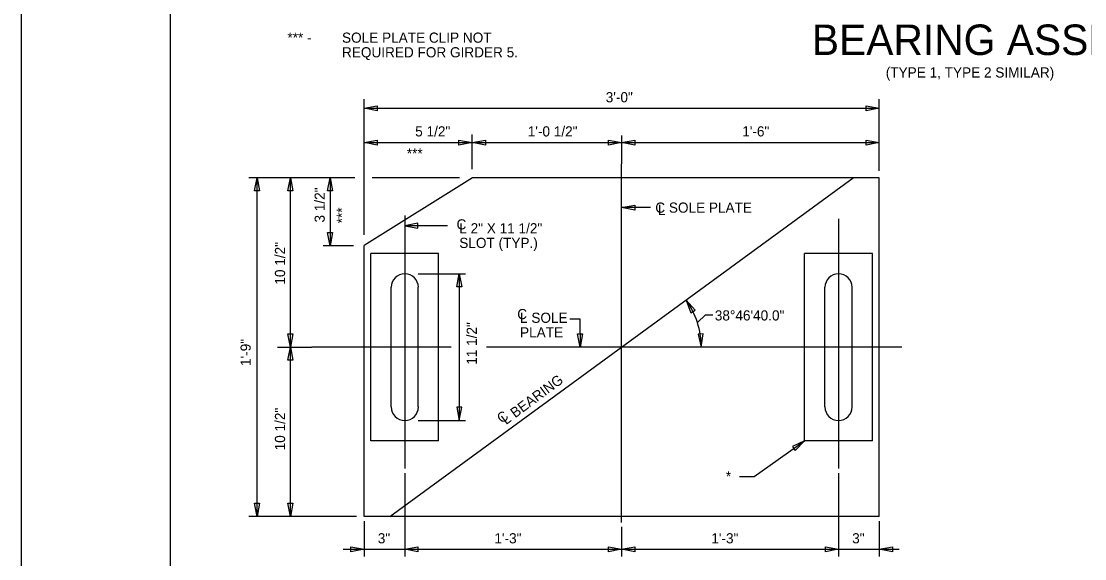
# Model space of a CAD drawing. Extents: x -125.5 to -89.4, y -5.1 to 16.9.
# Drawn here: x -125.53 to -112.46, y 3.75 to 10.36 of the extents above; entities that cross this region are included whole.
import ezdxf

# ---------------------------------------------------------------- set-up
doc = ezdxf.new("R2010")
doc.units = 0
for name, color, linetype in [('BR_AUTO DIMENSION', 7, 'Continuous'), ('BR_BORDER LINES', 7, 'Continuous'), ('BR_CENTER LINES', 7, 'Continuous'), ('BR_STRUCTURAL STEEL', 7, 'Continuous'), ('BR_TEXT', 7, 'Continuous'), ('Level 31', 7, 'Continuous')]:
    doc.layers.add(name, color=color, linetype=linetype)

msp = doc.modelspace()

# ---------------------------------------------------------------- linework, layer by layer
at = {"layer": 'BR_AUTO DIMENSION'}
for p, q in [((-121.317, 7.733), (-121.317, 9.402)), ((-121.317, 9.291), (-114.984, 9.291)), ((-114.984, 8.52), (-114.984, 9.402)), ((-119.988, 8.542), (-119.988, 8.967)), ((-118.151, 8.955), (-118.151, 8.607)), ((-121.317, 8.869), (-118.151, 8.869)), ((-118.151, 8.869), (-114.984, 8.869)), ((-121.433, 8.435), (-122.735, 8.435)), ((-122.633, 4.269), (-122.633, 8.435)), ((-122.223, 4.269), (-122.223, 8.435)), ((-121.736, 8.435), (-121.736, 7.599)), ((-120.143, 8.435), (-121.22, 8.435)), ((-117.797, 8.069), (-118.151, 8.069)), ((-120.293, 7.845), (-120.817, 7.845)), ((-121.447, 7.599), (-121.821, 7.599)), ((-120.653, 7.255), (-120.07, 7.255)), ((-120.148, 7.255), (-120.148, 5.449)), ((-118.788, 6.701), (-118.663, 6.701)), ((-118.663, 6.701), (-118.662, 6.352)), ((-117.219, 6.656), (-117.118, 6.748)), ((-117.118, 6.748), (-117.029, 6.748)), ((-122.383, 6.352), (-121.96, 6.352)), ((-120.653, 5.449), (-120.07, 5.449)), ((-116.523, 4.76), (-115.901, 5.199)), ((-120.817, 4.801), (-120.817, 3.778)), ((-116.701, 4.76), (-116.523, 4.76)), ((-115.484, 4.801), (-115.484, 3.778)), ((-121.411, 4.269), (-122.735, 4.269)), ((-121.317, 4.213), (-121.317, 3.778)), ((-114.984, 4.213), (-114.984, 3.778)), ((-118.151, 4.141), (-118.151, 3.778)), ((-121.574, 3.865), (-120.817, 3.865)), ((-120.817, 3.865), (-118.151, 3.865)), ((-118.151, 3.865), (-115.484, 3.865)), ((-115.484, 3.865), (-114.739, 3.865))]:
    msp.add_line(p, q, dxfattribs=at)
for points in [[(-121.155, 9.26), (-121.317, 9.291), (-121.155, 9.322)], [(-115.146, 9.322), (-114.984, 9.291), (-115.146, 9.26)], [(-121.155, 8.838), (-121.317, 8.869), (-121.155, 8.9)], [(-120.151, 8.9), (-119.988, 8.869), (-120.151, 8.838)], [(-119.826, 8.838), (-119.988, 8.869), (-119.826, 8.9)], [(-118.313, 8.9), (-118.151, 8.869), (-118.313, 8.838)], [(-117.988, 8.838), (-118.151, 8.869), (-117.988, 8.9)], [(-115.146, 8.9), (-114.984, 8.869), (-115.146, 8.838)], [(-122.665, 8.273), (-122.633, 8.435), (-122.602, 8.273)], [(-122.254, 8.273), (-122.223, 8.435), (-122.192, 8.273)], [(-121.767, 8.273), (-121.736, 8.435), (-121.705, 8.273)], [(-117.988, 8.037), (-118.151, 8.069), (-117.988, 8.1)], [(-120.655, 7.877), (-120.817, 7.845), (-120.655, 7.814)], [(-121.705, 7.761), (-121.736, 7.599), (-121.767, 7.761)], [(-120.179, 7.093), (-120.148, 7.255), (-120.117, 7.093)], [(-117.248, 6.808), (-117.358, 6.931), (-117.301, 6.776)], [(-122.192, 6.515), (-122.223, 6.352), (-122.254, 6.515)], [(-118.631, 6.515), (-118.662, 6.352), (-118.694, 6.515)], [(-117.211, 6.511), (-117.171, 6.351), (-117.148, 6.515)], [(-122.254, 6.19), (-122.223, 6.352), (-122.192, 6.19)], [(-120.179, 5.612), (-120.148, 5.449), (-120.117, 5.612)], [(-116.015, 5.08), (-115.901, 5.199), (-116.051, 5.131)], [(-122.602, 4.431), (-122.633, 4.269), (-122.665, 4.431)], [(-122.192, 4.431), (-122.223, 4.269), (-122.254, 4.431)], [(-121.48, 3.897), (-121.317, 3.865), (-121.48, 3.834)], [(-120.655, 3.834), (-120.817, 3.865), (-120.655, 3.897)], [(-118.313, 3.897), (-118.151, 3.865), (-118.313, 3.834)], [(-117.988, 3.834), (-118.151, 3.865), (-117.988, 3.897)], [(-115.646, 3.897), (-115.484, 3.865), (-115.646, 3.834)], [(-114.821, 3.834), (-114.984, 3.865), (-114.821, 3.897)]]:
    msp.add_lwpolyline(points, close=True, dxfattribs=at)
msp.add_arc((-118.165, 6.351), 0.994, 0, 35.8148, dxfattribs=at)
at = {"layer": 'BR_BORDER LINES'}
msp.add_line((-123.699, -4.566), (-123.699, 16.434), dxfattribs=at)
at = {"layer": 'BR_CENTER LINES'}
for p, q in [((-118.151, 6.352), (-118.151, 8.607)), ((-120.999, 4.269), (-115.302, 8.435)), ((-120.817, 7.97), (-120.817, 4.861)), ((-115.484, 7.93), (-115.484, 4.861)), ((-120.248, 6.352), (-121.96, 6.352)), ((-118.151, 6.352), (-119.814, 6.352)), ((-118.151, 4.195), (-118.151, 6.352)), ((-114.704, 6.352), (-118.151, 6.352))]:
    msp.add_line(p, q, dxfattribs=at)
at = {"layer": 'BR_STRUCTURAL STEEL'}
for p, q in [((-119.984, 8.435), (-121.317, 7.602)), ((-114.984, 8.435), (-119.984, 8.435)), ((-114.984, 4.269), (-114.984, 8.435)), ((-121.317, 4.269), (-121.317, 7.602)), ((-121.234, 5.199), (-121.234, 7.505)), ((-120.401, 7.505), (-121.234, 7.505)), ((-120.401, 5.199), (-120.401, 7.505)), ((-115.901, 5.199), (-115.901, 7.505)), ((-115.067, 7.505), (-115.901, 7.505)), ((-115.067, 5.199), (-115.067, 7.505)), ((-120.984, 5.616), (-120.984, 7.088)), ((-120.651, 5.616), (-120.651, 7.088)), ((-115.651, 5.616), (-115.651, 7.088)), ((-115.317, 5.616), (-115.317, 7.088)), ((-120.401, 5.199), (-121.234, 5.199)), ((-115.067, 5.199), (-115.901, 5.199)), ((-114.984, 4.269), (-121.317, 4.269))]:
    msp.add_line(p, q, dxfattribs=at)
for centre, start, end in [((-120.817, 7.088), 0, 180), ((-115.484, 7.088), 0, 180), ((-120.817, 5.616), 180, 360), ((-115.484, 5.616), 180, 360)]:
    msp.add_arc(centre, 0.167, start, end, dxfattribs=at)
at = {"layer": 'Level 31'}
msp.add_lwpolyline([(-125.533, 16.934), (-125.533, -5.066), (-89.533, -5.066), (-89.533, 16.934)], dxfattribs=at)

# ---------------------------------------------------------------- texts
at = {"layer": 'BR_AUTO DIMENSION'}
msp.add_text('(TYPE 1, TYPE 2 SIMILAR)', height=0.125, dxfattribs=at).set_placement((-114.903, 9.669))
at = {"layer": 'BR_TEXT'}
for s, height, rotation, p in [('*** -', 0.125, 360, (-122.26, 10.097)), ('SOLE PLATE CLIP NOT ', 0.125, 360, (-121.589, 10.097)), ('REQUIRED FOR GIRDER 5.', 0.125, 360, (-121.589, 9.917)), ('***', 0.125, 360, (-120.792, 8.672)), ('3 1/2"', 0.125, 90, (-121.801, 7.885)), ('C SOLE PLATE', 0.125, 360, (-117.737, 8.006)), ('***', 0.125, 90, (-121.528, 7.875)), ('L', 0.125, 360, (-117.704, 7.978)), ('C', 0.125, 0, (-120.181, 7.8)), ('L 2" X 11 1/2"', 0.125, 0, (-120.147, 7.752)), ('10 1/2"', 0.125, 90, (-122.289, 7.121)), ('SLOT (TYP.)', 0.125, 0, (-120.147, 7.572)), ('C', 0.125, 360, (-119.434, 6.696)), ('38%%D46\'40.0"', 0.12497, 360, (-117.005, 6.68)), ('L SOLE ', 0.125, 360, (-119.4, 6.651)), ('11 1/2"', 0.125, 90, (-119.931, 6.135)), ('PLATE', 0.125, 360, (-119.4, 6.471)), ('1\'-9"', 0.125, 90, (-122.712, 6.12)), ('L BEARING', 0.125, 36.6296, (-119.572, 5.392)), ('10 1/2"', 0.125, 90, (-122.289, 5.082)), ('C', 0.125, 36.6296, (-119.626, 5.408)), ('*', 0.125, 0, (-116.869, 4.7))]:
    msp.add_text(s, height=height, rotation=rotation, dxfattribs=at).set_placement(p)
for s, height, p in [('BEARING ASSEMBLY', 0.375, (-115.812, 9.946)), ('3\'-0"', 0.125, (-118.346, 9.364)), ('5 1/2"', 0.125, (-120.689, 8.944)), ('1\'-0 1/2"', 0.125, (-119.305, 8.944)), ('1\'-6"', 0.125, (-116.668, 8.944)), ('3"', 0.125, (-121.149, 3.938)), ('1\'-3"', 0.125, (-119.715, 3.938)), ('1\'-3"', 0.125, (-117.048, 3.938)), ('3"', 0.125, (-115.316, 3.938))]:
    msp.add_text(s, height=height, dxfattribs=at).set_placement(p)

doc.saveas('drawing.dxf')
